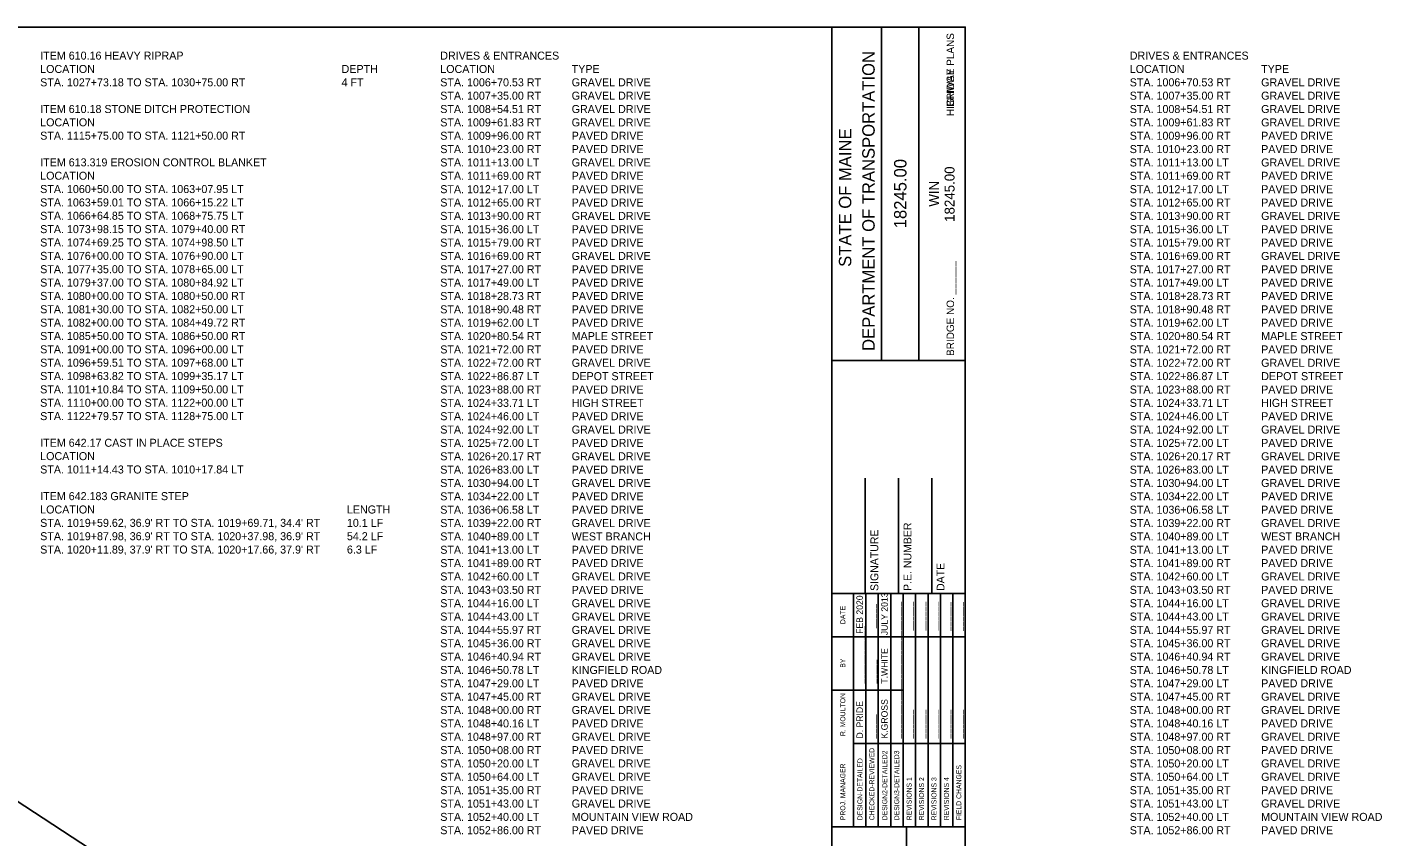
# Model space of a CAD drawing. Extents: x -831 to 3331, y -1004 to 250.
# Drawn here: x 591 to 1099, y -54 to 250 of the extents above; entities that cross this region are included whole.
import ezdxf

# ---------------------------------------------------------------- set-up
doc = ezdxf.new("R2010")
doc.units = 0
for name, color, linetype in [('BORDER', 7, 'Continuous'), ('BRIDGE_TITLE', 7, 'Continuous'), ('Default', 7, 'Continuous'), ('HIGHWAY_TITLE', 7, 'Continuous')]:
    doc.layers.add(name, color=color, linetype=linetype)

msp = doc.modelspace()

# ---------------------------------------------------------------- linework, layer by layer
at = {"layer": 'BORDER'}
for p, q in [((893.03, -275.31), (893.03, 249.69)), ((911.68, 124.68), (911.68, 249.68)), ((925.65, 124.68), (925.65, 249.68)), ((893.04, 124.66), (943.03, 124.66)), ((905.53, 37.21), (905.53, 80.45)), ((918.03, 37.21), (918.03, 80.45)), ((930.53, 37.21), (930.53, 80.45)), ((893.03, 37.21), (943.03, 37.21)), ((893.03, -50.29), (943.03, -50.29)), ((920.99, -225.29), (920.99, -50.29))]:
    msp.add_line(p, q, dxfattribs=at)
msp.add_lwpolyline([(143.03, 249.69), (943.03, 249.69), (943.03, -275.31), (143.03, -275.31)], close=True, dxfattribs=at)
for points in [[(901.11, 20.96), (901.11, 37.21)], [(905.77, -50.28), (905.77, 37.21)], [(910.43, 37.21), (910.43, -50.28)], [(915.09, -50.28), (915.09, 37.21)], [(919.75, -50.28), (919.75, 37.21)], [(924.4, -50.28), (924.4, 37.21)], [(929.06, -50.28), (929.06, 37.21)], [(933.72, -50.28), (933.72, 37.21)], [(938.38, -50.28), (938.38, 37.21)], [(901.11, -50.28), (901.11, 33.68)], [(893.03, 20.96), (943.03, 20.96)], [(893.03, 0.96), (901.11, 0.96)], [(901.11, 0.96), (919.74, 0.96)], [(901.11, -19.04), (943.03, -19.04)]]:
    msp.add_lwpolyline(points, dxfattribs=at)
at = {"layer": 'Default'}
msp.add_line((143.03, 249.69), (958.96, -283.29), dxfattribs=at)

# ---------------------------------------------------------------- texts
at = {"layer": 'BORDER'}
for s, height, p in [('DEPARTMENT OF TRANSPORTATION', 4.6588, (909.07, 128.22)), ('STATE OF MAINE', 4.6588, (900.31, 159.75)), ('18245.00', 4.659, (920.99, 174.22)), ('18245.00', 3.726, (939.01, 176.63)), ('WIN', 3.726, (933.22, 182.34)), ('SIGNATURE', 2.953, (910.43, 38.17)), ('P.E. NUMBER', 2.9528, (922.84, 38.17)), ('DATE', 2.953, (935.24, 38.17)), ('FEB 2020', 2.423, (904.65, 22.09)), ('JULY 2013', 2.423, (913.96, 21.57)), ('DATE', 1.857, (898.05, 25.74)), ('_____', 2.423, (909.12, 24.23)), ('______', 2.423, (918.44, 23.34)), ('______', 2.423, (923.09, 23.34)), ('______', 2.423, (927.75, 23.35)), ('______', 2.423, (932.41, 23.35)), ('______', 2.423, (937.07, 23.2)), ('______', 2.423, (941.73, 23.2)), ('____________', 2.4227, (904.65, 3.38)), ('____________', 2.4227, (918.44, 3.38)), ('T.WHITE', 2.423, (913.96, 3.38)), ('BY', 1.857, (898.05, 9.38)), ('_____', 2.423, (909.31, 3.38)), ('____________', 2.4227, (918.44, -17.18)), ('R. MOULTON', 1.864, (898.05, -16.28)), ('D. PRIDE', 2.423, (904.65, -17.18)), ('K.GROSS', 2.423, (913.96, -17.18)), ('_____', 2.423, (909.12, -17.18)), ('______', 2.423, (923.09, -17.18)), ('______', 2.423, (927.75, -17.18)), ('______', 2.423, (932.41, -17.18)), ('______', 2.423, (937.07, -17.18)), ('______', 2.423, (941.73, -17.18)), ('DESIGN-DETAILED', 1.8637, (904.47, -47.85)), ('CHECKED-REVIEWED', 1.8637, (908.94, -47.85)), ('DESIGN2-DETAILED2', 1.8637, (913.78, -47.85)), ('DESIGN3-DETAILED3', 1.8637, (918.25, -47.85)), ('PROJ. MANAGER', 1.8637, (898.05, -47.85)), ('FIELD CHANGES', 1.8637, (941.55, -47.85)), ('REVISIONS 1', 1.8637, (922.91, -47.85)), ('REVISIONS 2', 1.8637, (927.57, -47.85)), ('REVISIONS 3', 1.8637, (932.23, -47.85)), ('REVISIONS 4', 1.8637, (936.89, -47.85))]:
    msp.add_text(s, height=height, rotation=90, dxfattribs=at).set_placement(p)
at = {"layer": 'BRIDGE_TITLE'}
for s, p in [('BRIDGE PLANS', (938.82, 219.81)), ('BRIDGE NO. ______', (938.82, 126.34))]:
    msp.add_text(s, height=2.795, rotation=90, dxfattribs=at).set_placement(p)
at = {"layer": 'Default'}
for s, p in [('ITEM 610.16 HEAVY RIPRAP', (596.19, 237.49)), ('DRIVES & ENTRANCES', (746.19, 237.49)), ('DRIVES & ENTRANCES', (1004.7, 237.49)), ('LOCATION', (596.19, 232.48)), ('DEPTH', (709.19, 232.48)), ('LOCATION', (746.19, 232.48)), ('TYPE', (795.46, 232.48)), ('LOCATION', (1004.7, 232.48)), ('TYPE', (1053.97, 232.48)), ('STA. 1027+73.18 TO STA. 1030+75.00 RT', (596.19, 227.47)), ('4 FT', (709.19, 227.47)), ('STA. 1006+70.53 RT', (746.19, 227.47)), ('GRAVEL DRIVE', (795.46, 227.47)), ('STA. 1006+70.53 RT', (1004.7, 227.47)), ('GRAVEL DRIVE', (1053.97, 227.47)), ('STA. 1007+35.00 RT', (746.19, 222.46)), ('GRAVEL DRIVE', (795.46, 222.46)), ('STA. 1007+35.00 RT', (1004.7, 222.46)), ('GRAVEL DRIVE', (1053.97, 222.46)), ('ITEM 610.18 STONE DITCH PROTECTION', (596.19, 217.47)), ('STA. 1008+54.51 RT', (746.19, 217.45)), ('GRAVEL DRIVE', (795.46, 217.45)), ('STA. 1008+54.51 RT', (1004.7, 217.45)), ('GRAVEL DRIVE', (1053.97, 217.45)), ('LOCATION', (596.19, 212.46)), ('STA. 1009+61.83 RT', (746.19, 212.44)), ('GRAVEL DRIVE', (795.46, 212.44)), ('STA. 1009+61.83 RT', (1004.7, 212.44)), ('GRAVEL DRIVE', (1053.97, 212.44)), ('STA. 1115+75.00 TO STA. 1121+50.00 RT', (596.19, 207.45)), ('STA. 1009+96.00 RT', (746.19, 207.43)), ('PAVED DRIVE', (795.46, 207.43)), ('STA. 1009+96.00 RT', (1004.7, 207.43)), ('PAVED DRIVE', (1053.97, 207.43)), ('STA. 1010+23.00 RT', (746.19, 202.42)), ('PAVED DRIVE', (795.46, 202.42)), ('STA. 1010+23.00 RT', (1004.7, 202.42)), ('PAVED DRIVE', (1053.97, 202.42)), ('ITEM 613.319 EROSION CONTROL BLANKET', (596.19, 197.45)), ('STA. 1011+13.00 LT', (746.19, 197.41)), ('GRAVEL DRIVE', (795.46, 197.41)), ('STA. 1011+13.00 LT', (1004.7, 197.41)), ('GRAVEL DRIVE', (1053.97, 197.41)), ('LOCATION', (596.19, 192.44)), ('STA. 1011+69.00 RT', (746.19, 192.4)), ('PAVED DRIVE', (795.46, 192.4)), ('STA. 1011+69.00 RT', (1004.7, 192.4)), ('PAVED DRIVE', (1053.97, 192.4)), ('STA. 1060+50.00 TO STA. 1063+07.95 LT', (596.19, 187.43)), ('STA. 1012+17.00 LT', (746.19, 187.39)), ('PAVED DRIVE', (795.46, 187.39)), ('STA. 1012+17.00 LT', (1004.7, 187.39)), ('PAVED DRIVE', (1053.97, 187.39)), ('STA. 1063+59.01 TO STA. 1066+15.22 LT', (596.19, 182.42)), ('STA. 1012+65.00 RT', (746.19, 182.38)), ('PAVED DRIVE', (795.46, 182.38)), ('STA. 1012+65.00 RT', (1004.7, 182.38)), ('PAVED DRIVE', (1053.97, 182.38)), ('STA. 1066+64.85 TO STA. 1068+75.75 LT', (596.19, 177.41)), ('STA. 1013+90.00 RT', (746.19, 177.37)), ('GRAVEL DRIVE', (795.46, 177.37)), ('STA. 1013+90.00 RT', (1004.7, 177.37)), ('GRAVEL DRIVE', (1053.97, 177.37)), ('STA. 1073+98.15 TO STA. 1079+40.00 RT', (596.19, 172.4)), ('STA. 1015+36.00 LT', (746.19, 172.36)), ('PAVED DRIVE', (795.46, 172.36)), ('STA. 1015+36.00 LT', (1004.7, 172.36)), ('PAVED DRIVE', (1053.97, 172.36)), ('STA. 1074+69.25 TO STA. 1074+98.50 LT', (596.19, 167.39)), ('STA. 1015+79.00 RT', (746.19, 167.35)), ('PAVED DRIVE', (795.46, 167.35)), ('STA. 1015+79.00 RT', (1004.7, 167.35)), ('PAVED DRIVE', (1053.97, 167.35)), ('STA. 1076+00.00 TO STA. 1076+90.00 LT', (596.19, 162.38)), ('STA. 1016+69.00 RT', (746.19, 162.34)), ('GRAVEL DRIVE', (795.46, 162.34)), ('STA. 1016+69.00 RT', (1004.7, 162.34)), ('GRAVEL DRIVE', (1053.97, 162.34)), ('STA. 1077+35.00 TO STA. 1078+65.00 LT', (596.19, 157.37)), ('STA. 1017+27.00 RT', (746.19, 157.33)), ('PAVED DRIVE', (795.46, 157.33)), ('STA. 1017+27.00 RT', (1004.7, 157.33)), ('PAVED DRIVE', (1053.97, 157.33)), ('STA. 1079+37.00 TO STA. 1080+84.92 LT', (596.19, 152.36)), ('STA. 1017+49.00 LT', (746.19, 152.32)), ('PAVED DRIVE', (795.46, 152.32)), ('STA. 1017+49.00 LT', (1004.7, 152.32)), ('PAVED DRIVE', (1053.97, 152.32)), ('STA. 1080+00.00 TO STA. 1080+50.00 RT', (596.19, 147.35)), ('STA. 1018+28.73 RT', (746.19, 147.31)), ('PAVED DRIVE', (795.46, 147.31)), ('STA. 1018+28.73 RT', (1004.7, 147.31)), ('PAVED DRIVE', (1053.97, 147.31)), ('STA. 1081+30.00 TO STA. 1082+50.00 LT', (596.19, 142.34)), ('STA. 1018+90.48 RT', (746.19, 142.3)), ('PAVED DRIVE', (795.46, 142.3)), ('STA. 1018+90.48 RT', (1004.7, 142.3)), ('PAVED DRIVE', (1053.97, 142.3)), ('STA. 1082+00.00 TO STA. 1084+49.72 RT', (596.19, 137.33)), ('STA. 1019+62.00 LT', (746.19, 137.29)), ('PAVED DRIVE', (795.46, 137.29)), ('STA. 1019+62.00 LT', (1004.7, 137.29)), ('PAVED DRIVE', (1053.97, 137.29)), ('STA. 1085+50.00 TO STA. 1086+50.00 RT', (596.19, 132.32)), ('STA. 1020+80.54 RT', (746.19, 132.28)), ('MAPLE STREET', (795.46, 132.28)), ('STA. 1020+80.54 RT', (1004.7, 132.28)), ('MAPLE STREET', (1053.97, 132.28)), ('STA. 1091+00.00 TO STA. 1096+00.00 LT', (596.19, 127.31)), ('STA. 1021+72.00 RT', (746.19, 127.27)), ('PAVED DRIVE', (795.46, 127.27)), ('STA. 1021+72.00 RT', (1004.7, 127.27)), ('PAVED DRIVE', (1053.97, 127.27)), ('STA. 1096+59.51 TO STA. 1097+68.00 LT', (596.19, 122.3)), ('STA. 1022+72.00 RT', (746.19, 122.26)), ('GRAVEL DRIVE', (795.46, 122.26)), ('STA. 1022+72.00 RT', (1004.7, 122.26)), ('GRAVEL DRIVE', (1053.97, 122.26)), ('STA. 1098+63.82 TO STA. 1099+35.17 LT', (596.19, 117.29)), ('STA. 1022+86.87 LT', (746.19, 117.25)), ('DEPOT STREET', (795.46, 117.25)), ('STA. 1022+86.87 LT', (1004.7, 117.25)), ('DEPOT STREET', (1053.97, 117.25)), ('STA. 1101+10.84 TO STA. 1109+50.00 LT', (596.19, 112.28)), ('STA. 1023+88.00 RT', (746.19, 112.24)), ('PAVED DRIVE', (795.46, 112.24)), ('STA. 1023+88.00 RT', (1004.7, 112.24)), ('PAVED DRIVE', (1053.97, 112.24)), ('STA. 1110+00.00 TO STA. 1122+00.00 LT', (596.19, 107.27)), ('STA. 1024+33.71 LT', (746.19, 107.23)), ('HIGH STREET', (795.46, 107.23)), ('STA. 1024+33.71 LT', (1004.7, 107.23)), ('HIGH STREET', (1053.97, 107.23)), ('STA. 1122+79.57 TO STA. 1128+75.00 LT', (596.19, 102.26)), ('STA. 1024+46.00 LT', (746.19, 102.22)), ('PAVED DRIVE', (795.46, 102.22)), ('STA. 1024+46.00 LT', (1004.7, 102.22)), ('PAVED DRIVE', (1053.97, 102.22)), ('STA. 1024+92.00 LT', (746.19, 97.21)), ('GRAVEL DRIVE', (795.46, 97.21)), ('STA. 1024+92.00 LT', (1004.7, 97.21)), ('GRAVEL DRIVE', (1053.97, 97.21)), ('ITEM 642.17 CAST IN PLACE STEPS', (596.19, 92.26)), ('STA. 1025+72.00 LT', (746.19, 92.2)), ('PAVED DRIVE', (795.46, 92.2)), ('STA. 1025+72.00 LT', (1004.7, 92.2)), ('PAVED DRIVE', (1053.97, 92.2)), ('LOCATION', (596.19, 87.25)), ('STA. 1026+20.17 RT', (746.19, 87.19)), ('GRAVEL DRIVE', (795.46, 87.19)), ('STA. 1026+20.17 RT', (1004.7, 87.19)), ('GRAVEL DRIVE', (1053.97, 87.19)), ('STA. 1011+14.43 TO STA. 1010+17.84 LT', (596.19, 82.24)), ('STA. 1026+83.00 LT', (746.19, 82.18)), ('PAVED DRIVE', (795.46, 82.18)), ('STA. 1026+83.00 LT', (1004.7, 82.18)), ('PAVED DRIVE', (1053.97, 82.18)), ('STA. 1030+94.00 LT', (746.19, 77.17)), ('GRAVEL DRIVE', (795.46, 77.17)), ('STA. 1030+94.00 LT', (1004.7, 77.17)), ('GRAVEL DRIVE', (1053.97, 77.17)), ('ITEM 642.183 GRANITE STEP', (596.19, 72.24)), ('STA. 1034+22.00 LT', (746.19, 72.16)), ('PAVED DRIVE', (795.46, 72.16)), ('STA. 1034+22.00 LT', (1004.7, 72.16)), ('PAVED DRIVE', (1053.97, 72.16)), ('LOCATION', (596.19, 67.23)), ('LENGTH', (711.19, 67.23)), ('STA. 1036+06.58 LT', (746.19, 67.15)), ('PAVED DRIVE', (795.46, 67.15)), ('STA. 1036+06.58 LT', (1004.7, 67.15)), ('PAVED DRIVE', (1053.97, 67.15)), ("STA. 1019+59.62, 36.9' RT TO STA. 1019+69.71, 34.4' RT", (596.19, 62.22)), ('10.1 LF', (711.19, 62.22)), ('STA. 1039+22.00 RT', (746.19, 62.14)), ('GRAVEL DRIVE', (795.46, 62.14)), ('STA. 1039+22.00 RT', (1004.7, 62.14)), ('GRAVEL DRIVE', (1053.97, 62.14)), ("STA. 1019+87.98, 36.9' RT TO STA. 1020+37.98, 36.9' RT", (596.19, 57.21)), ('54.2 LF', (711.19, 57.21)), ('STA. 1040+89.00 LT', (746.19, 57.13)), ('WEST BRANCH', (795.46, 57.13)), ('STA. 1040+89.00 LT', (1004.7, 57.13)), ('WEST BRANCH', (1053.97, 57.13)), ("STA. 1020+11.89, 37.9' RT TO STA. 1020+17.66, 37.9' RT", (596.19, 52.2)), ('6.3 LF', (711.19, 52.2)), ('STA. 1041+13.00 LT', (746.19, 52.12)), ('PAVED DRIVE', (795.46, 52.12)), ('STA. 1041+13.00 LT', (1004.7, 52.12)), ('PAVED DRIVE', (1053.97, 52.12)), ('STA. 1041+89.00 RT', (746.19, 47.11)), ('PAVED DRIVE', (795.46, 47.11)), ('STA. 1041+89.00 RT', (1004.7, 47.11)), ('PAVED DRIVE', (1053.97, 47.11)), ('STA. 1042+60.00 LT', (746.19, 42.1)), ('GRAVEL DRIVE', (795.46, 42.1)), ('STA. 1042+60.00 LT', (1004.7, 42.1)), ('GRAVEL DRIVE', (1053.97, 42.1)), ('STA. 1043+03.50 RT', (746.19, 37.09)), ('PAVED DRIVE', (795.46, 37.09)), ('STA. 1043+03.50 RT', (1004.7, 37.09)), ('PAVED DRIVE', (1053.97, 37.09)), ('STA. 1044+16.00 LT', (746.19, 32.08)), ('GRAVEL DRIVE', (795.46, 32.08)), ('STA. 1044+16.00 LT', (1004.7, 32.08)), ('GRAVEL DRIVE', (1053.97, 32.08)), ('STA. 1044+43.00 LT', (746.19, 27.07)), ('GRAVEL DRIVE', (795.46, 27.07)), ('STA. 1044+43.00 LT', (1004.7, 27.07)), ('GRAVEL DRIVE', (1053.97, 27.07)), ('STA. 1044+55.97 RT', (746.19, 22.06)), ('GRAVEL DRIVE', (795.46, 22.06)), ('STA. 1044+55.97 RT', (1004.7, 22.06)), ('GRAVEL DRIVE', (1053.97, 22.06)), ('STA. 1045+36.00 RT', (746.19, 17.05)), ('GRAVEL DRIVE', (795.46, 17.05)), ('STA. 1045+36.00 RT', (1004.7, 17.05)), ('GRAVEL DRIVE', (1053.97, 17.05)), ('STA. 1046+40.94 RT', (746.19, 12.04)), ('GRAVEL DRIVE', (795.46, 12.04)), ('STA. 1046+40.94 RT', (1004.7, 12.04)), ('GRAVEL DRIVE', (1053.97, 12.04)), ('STA. 1046+50.78 LT', (746.19, 7.03)), ('KINGFIELD ROAD', (795.46, 7.03)), ('STA. 1046+50.78 LT', (1004.7, 7.03)), ('KINGFIELD ROAD', (1053.97, 7.03)), ('STA. 1047+29.00 LT', (746.19, 2.02)), ('STA. 1047+45.00 RT', (746.19, -2.99)), ('GRAVEL DRIVE', (795.46, -2.99)), ('PAVED DRIVE', (795.46, 2.02)), ('STA. 1047+29.00 LT', (1004.7, 2.02)), ('STA. 1047+45.00 RT', (1004.7, -2.99)), ('GRAVEL DRIVE', (1053.97, -2.99)), ('PAVED DRIVE', (1053.97, 2.02)), ('STA. 1048+00.00 RT', (746.19, -8)), ('GRAVEL DRIVE', (795.46, -8)), ('STA. 1048+00.00 RT', (1004.7, -8)), ('GRAVEL DRIVE', (1053.97, -8)), ('STA. 1048+40.16 LT', (746.19, -13.01)), ('PAVED DRIVE', (795.46, -13.01)), ('STA. 1048+40.16 LT', (1004.7, -13.01)), ('PAVED DRIVE', (1053.97, -13.01)), ('STA. 1048+97.00 RT', (746.19, -18.02)), ('GRAVEL DRIVE', (795.46, -18.02)), ('STA. 1048+97.00 RT', (1004.7, -18.02)), ('GRAVEL DRIVE', (1053.97, -18.02)), ('STA. 1050+08.00 RT', (746.19, -23.03)), ('PAVED DRIVE', (795.46, -23.03)), ('STA. 1050+08.00 RT', (1004.7, -23.03)), ('PAVED DRIVE', (1053.97, -23.03)), ('STA. 1050+20.00 LT', (746.19, -28.04)), ('GRAVEL DRIVE', (795.46, -28.04)), ('STA. 1050+20.00 LT', (1004.7, -28.04)), ('GRAVEL DRIVE', (1053.97, -28.04)), ('STA. 1050+64.00 LT', (746.19, -33.05)), ('GRAVEL DRIVE', (795.46, -33.05)), ('STA. 1050+64.00 LT', (1004.7, -33.05)), ('GRAVEL DRIVE', (1053.97, -33.05)), ('STA. 1051+35.00 RT', (746.19, -38.06)), ('PAVED DRIVE', (795.46, -38.06)), ('STA. 1051+35.00 RT', (1004.7, -38.06)), ('PAVED DRIVE', (1053.97, -38.06)), ('STA. 1051+43.00 LT', (746.19, -43.07)), ('GRAVEL DRIVE', (795.46, -43.07)), ('STA. 1051+43.00 LT', (1004.7, -43.07)), ('GRAVEL DRIVE', (1053.97, -43.07)), ('STA. 1052+40.00 LT', (746.19, -48.08)), ('MOUNTAIN VIEW ROAD', (795.46, -48.08)), ('STA. 1052+40.00 LT', (1004.7, -48.08)), ('MOUNTAIN VIEW ROAD', (1053.97, -48.08)), ('STA. 1052+86.00 RT', (746.19, -53.09)), ('PAVED DRIVE', (795.46, -53.09)), ('STA. 1052+86.00 RT', (1004.7, -53.09)), ('PAVED DRIVE', (1053.97, -53.09))]:
    msp.add_text(s, height=3, dxfattribs=at).set_placement(p)
at = {"layer": 'HIGHWAY_TITLE'}
msp.add_text('HIGHWAY PLANS', height=2.795, rotation=90, dxfattribs=at).set_placement((938.82, 216.27))

doc.saveas('drawing.dxf')
